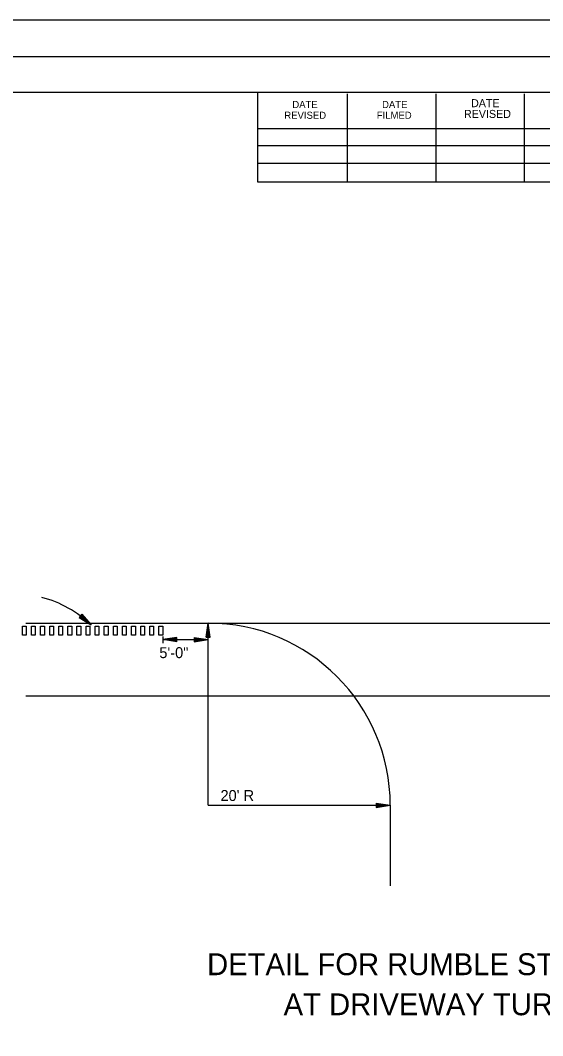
# Model space of a CAD drawing. Extents: x 3575 to 11445, y 9479 to 13278.
# Drawn here: x 8684 to 8971, y 10549 to 11106 of the extents above; entities that cross this region are included whole.
import ezdxf

# ---------------------------------------------------------------- set-up
doc = ezdxf.new("R2010")
doc.units = 0
for name, color, linetype in [('R_Dimension', 7, 'Continuous'), ('R_NoPlot', 7, 'Continuous'), ('STAMP_PE_CRAFTON-SIGNATURE', 7, 'Continuous'), ('STAMP_PRELIMINARY', 7, 'Continuous')]:
    doc.layers.add(name, color=color, linetype=linetype)

msp = doc.modelspace()

# ---------------------------------------------------------------- linework, layer by layer
at = {"layer": 'R_Dimension'}
for p, q in [((8717.64, 10779.93), (8716.14, 10778.15)), ((8716.14, 10778.15), (8722.82, 10774.06)), ((8716.27, 10778.3), (8721.83, 10774.89)), ((8716.4, 10778.45), (8720.81, 10775.75)), ((8716.52, 10778.6), (8719.82, 10776.58)), ((8716.65, 10778.75), (8718.82, 10777.42)), ((8716.77, 10778.9), (8717.83, 10778.26)), ((8717.01, 10779.18), (8717.83, 10778.26)), ((8717.13, 10779.33), (8718.82, 10777.42)), ((8717.26, 10779.48), (8719.82, 10776.58)), ((8717.39, 10779.63), (8720.81, 10775.75)), ((8717.51, 10779.78), (8721.83, 10774.89)), ((8717.64, 10779.93), (8722.82, 10774.06)), ((8785.89, 10767.34), (8787.06, 10775.08)), ((8785.89, 10767.34), (8787.06, 10775.08)), ((8786.09, 10767.34), (8787.06, 10773.79)), ((8786.09, 10767.34), (8787.06, 10773.79)), ((8788.22, 10767.34), (8787.06, 10775.08)), ((8788.22, 10767.34), (8787.06, 10775.08)), ((8788.02, 10767.34), (8787.06, 10773.79)), ((8788.02, 10767.34), (8787.06, 10773.79)), ((8769.8, 10767.15), (8762.06, 10765.99)), ((8769.8, 10766.96), (8763.35, 10765.99)), ((8769.8, 10764.83), (8769.8, 10767.15)), ((8779.31, 10767.15), (8787.06, 10765.99)), ((8779.31, 10767.15), (8779.31, 10764.83)), ((8779.31, 10766.96), (8785.76, 10765.99)), ((8785.89, 10767.34), (8788.22, 10767.34)), ((8785.89, 10767.34), (8788.22, 10767.34)), ((8786.29, 10767.34), (8787.06, 10772.45)), ((8786.29, 10767.34), (8787.06, 10772.45)), ((8786.48, 10767.34), (8787.06, 10771.17)), ((8786.48, 10767.34), (8787.06, 10771.17)), ((8786.68, 10767.34), (8787.06, 10769.85)), ((8786.68, 10767.34), (8787.06, 10769.85)), ((8786.87, 10767.34), (8787.06, 10768.56)), ((8786.87, 10767.34), (8787.06, 10768.56)), ((8787.83, 10767.34), (8787.06, 10772.45)), ((8787.83, 10767.34), (8787.06, 10772.45)), ((8787.63, 10767.34), (8787.06, 10771.17)), ((8787.63, 10767.34), (8787.06, 10771.17)), ((8787.44, 10767.34), (8787.06, 10769.85)), ((8787.44, 10767.34), (8787.06, 10769.85)), ((8787.24, 10767.34), (8787.06, 10768.56)), ((8787.24, 10767.34), (8787.06, 10768.56)), ((8769.8, 10764.83), (8762.06, 10765.99)), ((8769.8, 10765.02), (8763.35, 10765.99)), ((8769.8, 10766.76), (8764.68, 10765.99)), ((8769.8, 10765.22), (8764.68, 10765.99)), ((8769.8, 10766.57), (8765.97, 10765.99)), ((8769.8, 10765.42), (8765.97, 10765.99)), ((8769.8, 10766.37), (8767.28, 10765.99)), ((8769.8, 10765.62), (8767.28, 10765.99)), ((8769.8, 10766.18), (8768.58, 10765.99)), ((8769.8, 10765.81), (8768.58, 10765.99)), ((8779.31, 10766.76), (8784.43, 10765.99)), ((8779.31, 10766.57), (8783.14, 10765.99)), ((8779.31, 10766.37), (8781.83, 10765.99)), ((8779.31, 10766.18), (8780.54, 10765.99)), ((8779.31, 10764.83), (8787.06, 10765.99)), ((8779.31, 10765.61), (8781.83, 10765.99)), ((8779.31, 10765.22), (8784.43, 10765.99)), ((8779.31, 10765.02), (8785.76, 10765.99)), ((8779.31, 10765.42), (8783.14, 10765.99)), ((8779.31, 10765.81), (8780.54, 10765.99)), ((8879.33, 10676.23), (8887.07, 10675.06)), ((8879.33, 10676.23), (8879.33, 10673.9)), ((8879.33, 10676.23), (8887.07, 10675.06)), ((8879.33, 10676.23), (8879.33, 10673.9)), ((8879.33, 10676.03), (8885.78, 10675.06)), ((8879.33, 10676.03), (8885.78, 10675.06)), ((8879.33, 10675.84), (8884.45, 10675.06)), ((8879.33, 10675.84), (8884.45, 10675.06)), ((8879.33, 10675.64), (8883.16, 10675.06)), ((8879.33, 10675.64), (8883.16, 10675.06)), ((8879.33, 10675.44), (8881.84, 10675.06)), ((8879.33, 10675.44), (8881.84, 10675.06)), ((8879.33, 10675.25), (8880.55, 10675.06)), ((8879.33, 10675.25), (8880.55, 10675.06)), ((8879.33, 10673.9), (8887.07, 10675.06)), ((8879.33, 10674.69), (8881.84, 10675.06)), ((8879.33, 10674.29), (8884.45, 10675.06)), ((8879.33, 10674.1), (8885.78, 10675.06)), ((8879.33, 10674.49), (8883.16, 10675.06)), ((8879.33, 10674.88), (8880.55, 10675.06)), ((8879.33, 10673.9), (8887.07, 10675.06)), ((8879.33, 10674.69), (8881.84, 10675.06)), ((8879.33, 10674.29), (8884.45, 10675.06)), ((8879.33, 10674.1), (8885.78, 10675.06)), ((8879.33, 10674.49), (8883.16, 10675.06)), ((8879.33, 10674.88), (8880.55, 10675.06))]:
    msp.add_line(p, q, dxfattribs=at)
at = {"layer": 'R_NoPlot'}
msp.add_lwpolyline([(7582.64, 11086.17), (9249.34, 11086.17), (9249.34, 10019.49), (7582.64, 10019.49)], close=True, dxfattribs=at)
at = {"layer": 'STAMP_PE_CRAFTON-SIGNATURE'}
for p, q in [((8686.88, 10775.08), (9200.28, 10775.08)), ((8787.06, 10675.06), (8787.06, 10775.08)), ((8762.06, 10767.71), (8762.06, 10764.01)), ((8762.06, 10765.99), (8787.06, 10765.99)), ((8686.88, 10735.07), (9200.28, 10735.07)), ((8787.06, 10675.06), (8887.07, 10675.06)), ((8887.07, 10675.06), (8887.07, 10630.78))]:
    msp.add_line(p, q, dxfattribs=at)
for points in [[(8684.97, 10768.41), (8684.97, 10773.41), (8687.05, 10773.41), (8687.05, 10768.41), (8684.97, 10768.41)], [(8689.97, 10768.41), (8689.97, 10773.41), (8692.05, 10773.41), (8692.05, 10768.41), (8689.97, 10768.41)], [(8694.97, 10768.41), (8694.97, 10773.41), (8697.05, 10773.41), (8697.05, 10768.41), (8694.97, 10768.41)], [(8699.97, 10768.41), (8699.97, 10773.41), (8702.05, 10773.41), (8702.05, 10768.41), (8699.97, 10768.41)], [(8704.97, 10768.41), (8704.97, 10773.41), (8707.05, 10773.41), (8707.05, 10768.41), (8704.97, 10768.41)], [(8709.97, 10768.41), (8709.97, 10773.41), (8712.05, 10773.41), (8712.05, 10768.41), (8709.97, 10768.41)], [(8714.97, 10768.41), (8714.97, 10773.41), (8717.05, 10773.41), (8717.05, 10768.41), (8714.97, 10768.41)], [(8719.97, 10768.41), (8719.97, 10773.41), (8722.05, 10773.41), (8722.05, 10768.41), (8719.97, 10768.41)], [(8724.97, 10768.41), (8724.97, 10773.41), (8727.05, 10773.41), (8727.05, 10768.41), (8724.97, 10768.41)], [(8729.97, 10768.41), (8729.97, 10773.41), (8732.06, 10773.41), (8732.06, 10768.41), (8729.97, 10768.41)], [(8734.97, 10768.41), (8734.97, 10773.41), (8737.06, 10773.41), (8737.06, 10768.41), (8734.97, 10768.41)], [(8739.97, 10768.41), (8739.97, 10773.41), (8742.06, 10773.41), (8742.06, 10768.41), (8739.97, 10768.41)], [(8744.97, 10768.41), (8744.97, 10773.41), (8747.06, 10773.41), (8747.06, 10768.41), (8744.97, 10768.41)], [(8749.97, 10768.41), (8749.97, 10773.41), (8752.06, 10773.41), (8752.06, 10768.41), (8749.97, 10768.41)], [(8754.97, 10768.41), (8754.97, 10773.41), (8757.06, 10773.41), (8757.06, 10768.41), (8754.97, 10768.41)], [(8759.97, 10768.41), (8759.97, 10773.41), (8762.06, 10773.41), (8762.06, 10768.41), (8759.97, 10768.41)]]:
    msp.add_lwpolyline(points, dxfattribs=at)
for centre, radius, start, end in [((8679.77, 10728.75), 62.5, 46.4613, 75.2786), ((8787.06, 10675.06), 100.02, 0, 90)]:
    msp.add_arc(centre, radius, start, end, dxfattribs=at)
at = {"layer": 'STAMP_PRELIMINARY'}
for p, q in [((9248.58, 11106.1), (7488.58, 11106.1)), ((7644.68, 11066.7), (9225.58, 11066.7)), ((8814.28, 11017.3), (8814.28, 11066.7)), ((8863.58, 11017.3), (8863.58, 11065.7)), ((8912.38, 11017.3), (8912.38, 11065.7)), ((8960.78, 11017.3), (8960.78, 11065.7)), ((8814.28, 11046.6), (9010.08, 11046.6)), ((8814.28, 11037.3), (9010.08, 11037.3)), ((8814.28, 11027.6), (9010.08, 11027.6)), ((9225.58, 11017.3), (8814.28, 11017.3))]:
    msp.add_line(p, q, dxfattribs=at)

# ---------------------------------------------------------------- texts
at = {"layer": 'STAMP_PE_CRAFTON-SIGNATURE'}
for s, height, p in [('5\'-0"', 6, (8760.2, 10755.86)), ("20' R", 6, (8793.79, 10677.4)), ('DETAIL FOR RUMBLE STRIP GAP', 12.0003, (8786.44, 10581.75)), ('AT DRIVEWAY TURNOUTS', 12.0003, (8828.5, 10559.75))]:
    msp.add_text(s, height=height, dxfattribs=at).set_placement(p)
at = {"layer": 'STAMP_PRELIMINARY'}
for s, height, p in [('DATE', 4.396, (8931.48, 11058.4)), ('DATE', 3.91, (8833.28, 11057.9)), ('DATE', 3.91, (8882.58, 11057.9)), ('REVISED', 4.396, (8927.58, 11052.5)), ('REVISED', 3.91, (8828.88, 11052)), ('FILMED', 3.91, (8879.68, 11052))]:
    msp.add_text(s, height=height, dxfattribs=at).set_placement(p)

doc.saveas('drawing.dxf')
